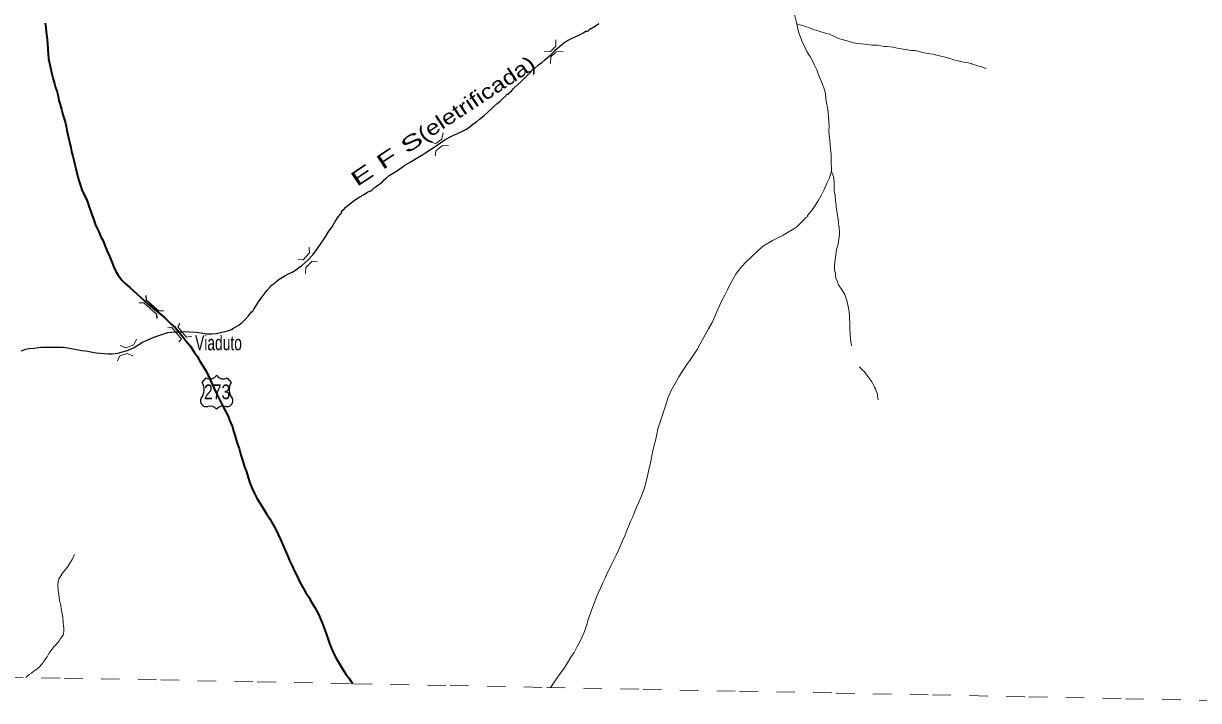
# Model space of a CAD drawing. Extents: x 781.9 to 808.1, y 7453.3 to 7481.5.
# Drawn here: x 787.99 to 794.37, y 7453.56 to 7457.23 of the extents above; entities that cross this region are included whole.
import ezdxf
from ezdxf.enums import TextEntityAlignment as Align

# ---------------------------------------------------------------- set-up
doc = ezdxf.new("R2010")
doc.units = 0
doc.header["$LTSCALE"] = 0.032
for name, pattern in [('DOTTED', [1.5, 0.3, -1.2]), ('LONG_DASHED', [7.5, 6, -1.5]), ('MEDIUM_DASHED', [4.5, 3, -1.5]), ('SHORT_DASHED', [2.7, 1.5, -1.2])]:
    doc.linetypes.add(name, pattern=pattern)
for name, color, linetype, lineweight in [('10', 7, 'Continuous', 25), ('11', 7, 'Continuous', 13), ('12', 7, 'Continuous', 25), ('15', 7, 'Continuous', 25), ('2', 7, 'Continuous', 35), ('35', 7, 'SHORT_DASHED', 13), ('5', 7, 'LONG_DASHED', 13), ('6', 7, 'MEDIUM_DASHED', 13), ('7', 7, 'DOTTED', 13)]:
    doc.layers.add(name, color=color, linetype=linetype, lineweight=lineweight)
doc.layers.add('61', color=7, linetype='Continuous')

msp = doc.modelspace()

# ---------------------------------------------------------------- linework, layer by layer
at = {"layer": '10'}
for p, q in [((788.657, 7455.7586), (788.6587, 7455.7337)), ((788.7282, 7455.6727), (788.6587, 7455.7337)), ((788.715, 7455.6576), (788.7165, 7455.6328)), ((788.753, 7455.6743), (788.7282, 7455.6727))]:
    msp.add_line(p, q, dxfattribs=at)
msp.add_lwpolyline([(788.715, 7455.6576), (788.6455, 7455.7187), (788.6205, 7455.7171)], dxfattribs=at)
at = {"layer": '11'}
for points in [[(790.8811, 7457.1447), (790.8806, 7457.1107), (790.8528, 7457.082), (790.8178, 7457.0834)], [(790.8532, 7457.0173), (790.8547, 7457.0532), (790.8835, 7457.081), (790.9213, 7457.0815)], [(790.195, 7456.5928), (790.2309, 7456.5838), (790.2624, 7456.6065), (790.2705, 7456.6399)], [(790.2986, 7456.5709), (790.2662, 7456.5716), (790.2294, 7456.544), (790.2263, 7456.5159)], [(789.4827, 7455.9531), (789.5104, 7455.9511), (789.5448, 7455.9901), (789.5428, 7456.0213)], [(789.5882, 7455.9414), (789.5599, 7455.944), (789.5244, 7455.9102), (789.5229, 7455.8784)], [(788.818, 7455.5608), (788.7961, 7455.587), (788.7759, 7455.5831)], [(788.8364, 7455.5069), (788.8503, 7455.5221), (788.818, 7455.5608)], [(788.8418, 7455.6062), (788.83, 7455.589), (788.8525, 7455.5619)], [(788.8525, 7455.5619), (788.8777, 7455.5317), (788.907, 7455.5383)], [(788.5186, 7455.4877), (788.5492, 7455.4746), (788.5915, 7455.49), (788.606, 7455.5212)], [(788.5037, 7455.4044), (788.5168, 7455.4316), (788.5551, 7455.4437), (788.5864, 7455.4306)]]:
    msp.add_lwpolyline(points, dxfattribs=at)
at = {"layer": '12'}
for p, q in [((788.9632, 7455.2866), (788.9841, 7455.3109)), ((788.9632, 7455.2866), (788.9841, 7455.3109)), ((789.0412, 7455.324), (789.0416, 7455.3236)), ((789.0412, 7455.324), (789.0416, 7455.3236)), ((789.0984, 7455.3109), (789.1193, 7455.2868)), ((789.0984, 7455.3109), (789.1193, 7455.2868))]:
    msp.add_line(p, q, dxfattribs=at)
for centre, radius, start, end in [((789.0049, 7455.351), 0.0452, 242.52866, 323.41613), ((789.0049, 7455.351), 0.0452, 242.52866, 323.41613), ((789.0775, 7455.351), 0.0452, 217.23651, 297.49117), ((789.0775, 7455.351), 0.0452, 217.23651, 297.49117), ((788.9, 7455.2484), 0.0738, 320.67544, 31.14191), ((788.9, 7455.2484), 0.0738, 320.67544, 31.14191), ((789.1824, 7455.2484), 0.0738, 148.68696, 219.32477), ((789.1824, 7455.2484), 0.0738, 148.68696, 219.32477), ((788.9852, 7455.1868), 0.0316, 151.50035, 286.50661), ((788.9852, 7455.1868), 0.0316, 151.50035, 286.50661), ((789.0973, 7455.1868), 0.0316, 253.49417, 28.49965), ((789.0973, 7455.1868), 0.0316, 253.49417, 28.49965), ((789.0072, 7455.1151), 0.0433, 38.34716, 107.68663), ((789.0072, 7455.1151), 0.0433, 38.34716, 107.68663), ((789.0752, 7455.1151), 0.0433, 72.31281, 141.65284), ((789.0752, 7455.1151), 0.0433, 72.31281, 141.65284)]:
    msp.add_arc(centre, radius, start, end, dxfattribs=at)
at = {"layer": '15'}
for points in [[(790.6156, 7456.8521), (790.6253, 7456.8496), (790.627, 7456.8561), (790.6351, 7456.8634), (790.64, 7456.8675), (790.6521, 7456.8813), (790.6756, 7456.9032), (790.6927, 7456.9186), (790.7073, 7456.934), (790.7219, 7456.9486), (790.7437, 7456.968), (790.7478, 7456.9737), (790.751, 7456.9818), (790.7551, 7456.9818), (790.7584, 7456.9859), (790.764, 7456.9875), (790.7875, 7457.0102), (790.8054, 7457.0231), (790.8216, 7457.037), (790.8561, 7457.0666), (790.8785, 7457.0898), (790.9114, 7457.1178), (790.921, 7457.125), (790.9221, 7457.1269), (790.9448, 7457.1424), (790.9659, 7457.1529), (790.9862, 7457.1618), (791.0065, 7457.1707), (791.0283, 7457.1813), (791.0461, 7457.1942), (791.0502, 7457.191), (791.0591, 7457.1934), (791.0624, 7457.2007), (791.0705, 7457.2064), (791.0737, 7457.2072), (791.0778, 7457.2104), (791.0859, 7457.2145), (791.0891, 7457.2161), (791.0973, 7457.2218), (791.1151, 7457.234)], [(790.5321, 7456.7718), (790.5476, 7456.7856), (790.5637, 7456.7994), (790.5792, 7456.8132), (790.5946, 7456.827), (790.6108, 7456.8416), (790.6156, 7456.8521)], [(788.8525, 7455.5619), (788.8597, 7455.5622), (788.9302, 7455.559), (788.9903, 7455.5502), (789.0144, 7455.5502), (789.0384, 7455.5526), (789.0622, 7455.5573), (789.0849, 7455.5622), (789.1068, 7455.5687), (789.1182, 7455.5727), (789.1222, 7455.5743), (789.1246, 7455.5735), (789.1287, 7455.5792), (789.1579, 7455.5954), (789.1774, 7455.61), (789.1952, 7455.6278), (789.2114, 7455.6457), (789.2325, 7455.6708), (789.2357, 7455.67), (789.2406, 7455.6813), (789.2681, 7455.7235), (789.2819, 7455.743), (789.299, 7455.7657), (789.3152, 7455.7867), (789.3338, 7455.807), (789.3395, 7455.8143), (789.346, 7455.8176), (789.3709, 7455.8392), (789.3885, 7455.852), (789.4077, 7455.8632), (789.4303, 7455.8751), (789.4514, 7455.8857), (789.4684, 7455.8962), (789.4855, 7455.9084), (789.5033, 7455.9213), (789.5354, 7455.9501), (789.5634, 7455.9797), (789.5891, 7456.0125), (789.6051, 7456.0365), (789.6316, 7456.0757), (789.6493, 7456.1069), (789.6671, 7456.1305), (789.6841, 7456.1589), (789.7027, 7456.1864), (789.7206, 7456.2092), (789.7206, 7456.2124), (789.7181, 7456.2132), (789.7198, 7456.2197), (789.7279, 7456.2213), (789.7311, 7456.227), (789.7359, 7456.2286), (789.7367, 7456.2335), (789.7611, 7456.2546), (789.7806, 7456.2683), (789.7992, 7456.2821), (789.8179, 7456.2927), (789.8381, 7456.304), (789.8568, 7456.317), (789.8746, 7456.3267), (789.8762, 7456.3251), (789.8843, 7456.3316), (789.8843, 7456.3324), (789.8884, 7456.3357), (789.8981, 7456.3437), (789.9038, 7456.3478), (789.9168, 7456.3567), (789.9265, 7456.364), (789.9403, 7456.3754), (789.9508, 7456.3851), (789.9613, 7456.3957), (789.9768, 7456.4094), (790.0033, 7456.4262), (790.0281, 7456.4398), (790.0626, 7456.4646), (790.087, 7456.4792), (790.1048, 7456.4905), (790.1227, 7456.501), (790.1413, 7456.5124), (790.16, 7456.5237), (790.1714, 7456.5308), (790.2068, 7456.554), (790.2427, 7456.578), (790.2804, 7456.6044), (790.3148, 7456.6228), (790.3469, 7456.6372), (790.3749, 7456.6492), (790.3958, 7456.6604), (790.4178, 7456.6762), (790.4332, 7456.6892), (790.4503, 7456.7013), (790.4673, 7456.7143), (790.4922, 7456.7343), (790.513, 7456.7535), (790.5321, 7456.7718)], [(788.6395, 7455.5058), (788.6633, 7455.516), (788.6836, 7455.5257), (788.7055, 7455.5346), (788.7282, 7455.5411), (788.7379, 7455.5446), (788.7772, 7455.5574)], [(788.7772, 7455.5574), (788.8116, 7455.5606), (788.818, 7455.5608), (788.8368, 7455.5614), (788.8525, 7455.5619)], [(787.9808, 7455.458), (788.0057, 7455.4668), (788.0217, 7455.47), (788.0513, 7455.4732), (788.0882, 7455.478), (788.1153, 7455.4787), (788.1396, 7455.4787), (788.1639, 7455.4787), (788.1866, 7455.4779), (788.2093, 7455.4779), (788.2336, 7455.4738), (788.2904, 7455.4641), (788.3099, 7455.4608), (788.3293, 7455.4584), (788.3488, 7455.4552), (788.3682, 7455.4511), (788.3877, 7455.4471), (788.4071, 7455.4446), (788.4542, 7455.4422), (788.472, 7455.4422), (788.4898, 7455.4438), (788.5061, 7455.4462), (788.5161, 7455.4482), (788.5578, 7455.4602), (788.593, 7455.4754), (788.6187, 7455.4922), (788.6395, 7455.5058)]]:
    msp.add_lwpolyline(points, dxfattribs=at)
at = {"layer": '2'}
for points in [[(788.1104, 7457.2364), (788.1136, 7457.2121), (788.1161, 7457.1894), (788.1218, 7457.1486), (788.1242, 7457.1238), (788.1267, 7457.067), (788.1284, 7457.043), (788.1372, 7457.003), (788.1436, 7456.977), (788.1485, 7456.9543), (788.155, 7456.9316), (788.1607, 7456.9089), (788.1671, 7456.8862), (788.1761, 7456.8618), (788.1817, 7456.8391), (788.1858, 7456.8164), (788.1931, 7456.7937), (788.1996, 7456.7694), (788.2052, 7456.7451), (788.2126, 7456.7224), (788.219, 7456.6997), (788.2239, 7456.677), (788.2288, 7456.6543), (788.2336, 7456.63), (788.2385, 7456.6073), (788.2442, 7456.5846), (788.2499, 7456.5619), (788.2539, 7456.5392), (788.2612, 7456.5148), (788.2661, 7456.4921), (788.2709, 7456.4694), (788.2774, 7456.4467), (788.2831, 7456.424), (788.2888, 7456.3997), (788.2953, 7456.377), (788.3025, 7456.3543), (788.309, 7456.3316), (788.3204, 7456.3089), (788.3333, 7456.2846), (788.3431, 7456.2603), (788.3496, 7456.2376), (788.3577, 7456.2149), (788.365, 7456.1922), (788.3747, 7456.1695), (788.382, 7456.1451), (788.3925, 7456.1224), (788.4031, 7456.0997), (788.412, 7456.077)], [(788.412, 7456.077), (788.425, 7456.0543), (788.4339, 7456.03), (788.4444, 7456.0073), (788.4461, 7456.0016), (788.459, 7455.9716), (788.4736, 7455.936)], [(788.4736, 7455.936), (788.4825, 7455.9116), (788.4939, 7455.8889), (788.5077, 7455.8694), (788.5271, 7455.8419), (788.5433, 7455.8249), (788.5701, 7455.8021), (788.5895, 7455.7843), (788.6082, 7455.7665), (788.6285, 7455.7486), (788.6495, 7455.73), (788.6706, 7455.7097), (788.6925, 7455.6911), (788.7144, 7455.6724), (788.7363, 7455.6562), (788.7557, 7455.64), (788.7744, 7455.6221), (788.7946, 7455.6035), (788.8166, 7455.584), (788.8368, 7455.5614)], [(788.8368, 7455.5614), (788.8384, 7455.5597), (788.8604, 7455.5322), (788.8749, 7455.5111), (788.8984, 7455.4827), (788.9195, 7455.4511), (788.935, 7455.43), (788.9503, 7455.4025), (788.9633, 7455.3814), (788.9819, 7455.3506), (788.9933, 7455.3279), (788.9982, 7455.3187), (789.0159, 7455.2811), (789.0359, 7455.2347), (789.0736, 7455.1611), (789.1065, 7455.0963), (789.1092, 7455.0879), (789.1157, 7455.0701), (789.1263, 7455.0457), (789.1328, 7455.023), (789.1392, 7455.0003), (789.1474, 7454.976), (789.1547, 7454.9517), (789.1627, 7454.9274), (789.1716, 7454.8914), (789.1828, 7454.8594), (789.1928, 7454.8285), (789.2025, 7454.8009), (789.2122, 7454.7717), (789.2211, 7454.7425), (789.2317, 7454.7149), (789.2446, 7454.6874), (789.26, 7454.6582), (789.2779, 7454.629), (789.2949, 7454.6014), (789.3111, 7454.5739), (789.3289, 7454.5463), (789.3452, 7454.5171), (789.3622, 7454.4896), (789.3743, 7454.462), (789.3881, 7454.4344), (789.4003, 7454.4052), (789.4133, 7454.376), (789.4254, 7454.3485), (789.4368, 7454.3209), (789.4506, 7454.2917), (789.4635, 7454.2625), (789.4773, 7454.235), (789.4911, 7454.2074), (789.5065, 7454.1782), (789.5235, 7454.149), (789.5414, 7454.1215), (789.556, 7454.0939), (789.5738, 7454.0663), (789.5939, 7454.0295), (789.6139, 7453.9831), (789.6354, 7453.9253), (789.6443, 7453.8977), (789.6533, 7453.8701), (789.6638, 7453.8426), (789.6767, 7453.815), (789.6922, 7453.7874), (789.7068, 7453.7599), (789.7246, 7453.7323), (789.7416, 7453.7047), (789.7611, 7453.678), (789.7765, 7453.6553), (789.7789, 7453.6524)]]:
    msp.add_lwpolyline(points, dxfattribs=at)
at = {"layer": '35'}
msp.add_lwpolyline([(794.4714, 7453.5611), (793.9481, 7453.5713), (793.4247, 7453.5816), (792.9014, 7453.5918), (792.378, 7453.602), (791.8547, 7453.6122), (791.3314, 7453.6223), (790.808, 7453.6325), (790.2847, 7453.6426), (789.7614, 7453.6527), (789.238, 7453.6628), (788.7147, 7453.6729), (788.1914, 7453.6829), (787.668, 7453.6929)], dxfattribs=at)
at = {"layer": '5'}
for points in [[(792.0097, 7457.6862), (792.0233, 7457.6598), (792.0312, 7457.645), (792.0442, 7457.624), (792.0564, 7457.6029), (792.0677, 7457.5802), (792.0815, 7457.5575), (792.0912, 7457.5364), (792.1018, 7457.5153), (792.1099, 7457.4942), (792.118, 7457.4715), (792.1253, 7457.4488), (792.1326, 7457.4278), (792.1391, 7457.4067), (792.1456, 7457.3856), (792.152, 7457.3645), (792.1585, 7457.3418), (792.1642, 7457.3207), (792.1707, 7457.2997), (792.1779, 7457.2755), (792.1883, 7457.2315)], [(792.1883, 7457.2315), (792.1971, 7457.1883), (792.2163, 7457.1395), (792.2307, 7457.1083), (792.2436, 7457.0824), (792.259, 7457.0564), (792.2728, 7457.0321), (792.2842, 7457.0078), (792.2972, 7456.9818), (792.3061, 7456.9559), (792.3174, 7456.93), (792.3272, 7456.9056), (792.3361, 7456.8797), (792.3434, 7456.8537), (792.3466, 7456.8278), (792.3491, 7456.8035), (792.3547, 7456.7791), (792.3588, 7456.7532), (792.3604, 7456.7273), (792.362, 7456.7013), (792.3637, 7456.677), (792.3629, 7456.6527), (792.3645, 7456.6267), (792.3669, 7456.6008), (792.3702, 7456.5748), (792.3718, 7456.5505), (792.3742, 7456.5262), (792.3758, 7456.5002), (792.3758, 7456.4743), (792.3766, 7456.4484), (792.3775, 7456.4305)], [(792.3775, 7456.4305), (792.3734, 7456.4224), (792.3653, 7456.3965), (792.3539, 7456.3705), (792.3393, 7456.3373), (792.3223, 7456.3048), (792.3045, 7456.2724), (792.285, 7456.2408), (792.2688, 7456.2181), (792.2469, 7456.1922), (792.2477, 7456.1873), (792.238, 7456.1816), (792.2275, 7456.1687), (792.1893, 7456.1313), (792.1723, 7456.1208), (792.1334, 7456.0964), (792.1083, 7456.0827), (792.0896, 7456.073), (792.0568, 7456.0573), (792.0087, 7456.0285), (791.9799, 7456.0037), (791.943, 7455.9677), (791.9413, 7455.9659), (791.9077, 7455.9347), (791.878, 7455.9003), (791.8577, 7455.8743), (791.8423, 7455.8451), (791.8261, 7455.816), (791.8123, 7455.7884), (791.7977, 7455.7608), (791.7823, 7455.7316), (791.7693, 7455.7025), (791.7564, 7455.6749), (791.7442, 7455.6441), (791.7298, 7455.6113), (791.709, 7455.5777), (791.6634, 7455.4961), (791.6477, 7455.4657), (791.6291, 7455.4381), (791.6112, 7455.4106), (791.5918, 7455.3846), (791.5699, 7455.3505), (791.5488, 7455.3173), (791.5286, 7455.2809), (791.5078, 7455.2425)], [(791.5078, 7455.2425), (791.4894, 7455.2017), (791.4791, 7455.1706), (791.4702, 7455.143), (791.4613, 7455.1155), (791.4523, 7455.0895), (791.4434, 7455.062)], [(791.4434, 7455.062), (791.4353, 7455.0344), (791.4288, 7455.0068), (791.4232, 7454.9793), (791.4159, 7454.9517), (791.4094, 7454.9241), (791.4045, 7454.8966), (791.3988, 7454.869), (791.3923, 7454.8414), (791.3859, 7454.8139), (791.3802, 7454.7863), (791.3722, 7454.7487), (791.3602, 7454.7103), (791.3426, 7454.6623), (791.3299, 7454.6339), (791.3186, 7454.6095), (791.308, 7454.5836), (791.2983, 7454.5577), (791.2869, 7454.5317), (791.2756, 7454.5058), (791.2651, 7454.4798), (791.2553, 7454.4539), (791.2432, 7454.4279), (791.2318, 7454.402), (791.2205, 7454.376), (791.2091, 7454.3501), (791.1953, 7454.3242), (791.184, 7454.2982), (791.171, 7454.2723), (791.1588, 7454.2479), (791.1475, 7454.222), (791.1353, 7454.1961), (791.1232, 7454.1701), (791.1102, 7454.1442), (791.1005, 7454.1182), (791.0907, 7454.0923), (791.081, 7454.0663), (791.0713, 7454.0404), (791.0616, 7454.0144), (791.0583, 7454.0055), (791.0486, 7453.9739), (791.0364, 7453.9358), (791.0218, 7453.9026), (791.0105, 7453.8766), (790.9959, 7453.8507), (790.9829, 7453.8247), (790.9805, 7453.8207), (790.9635, 7453.7963), (790.9383, 7453.7566), (790.9221, 7453.7307), (790.9043, 7453.7071), (790.8856, 7453.6779), (790.8646, 7453.6496), (790.854, 7453.6342), (790.8522, 7453.6316)]]:
    msp.add_lwpolyline(points, dxfattribs=at)
at = {"layer": '6'}
for points in [[(793.2158, 7456.9883), (793.2117, 7456.9899), (793.1923, 7456.998), (793.1704, 7457.0045), (793.1363, 7457.0159), (793.1339, 7457.0167), (793.1177, 7457.0207), (793.1015, 7457.0231), (793.0853, 7457.0264), (793.0707, 7457.0304), (793.0561, 7457.0337), (793.039, 7457.0361), (793.0317, 7457.041), (793.0188, 7457.0434), (792.9888, 7457.0532), (792.9863, 7457.0531), (792.9701, 7457.0564), (792.9555, 7457.0605), (792.9409, 7457.0645), (792.9263, 7457.0677), (792.9117, 7457.0694), (792.8972, 7457.071), (792.8745, 7457.0767), (792.8299, 7457.0872), (792.8258, 7457.0872), (792.8112, 7457.0872), (792.7966, 7457.0888), (792.782, 7457.0921), (792.7658, 7457.0945), (792.7496, 7457.0977), (792.7334, 7457.101), (792.7091, 7457.105), (792.679, 7457.1083), (792.675, 7457.1083), (792.6604, 7457.1099), (792.6442, 7457.1131), (792.628, 7457.1156), (792.6118, 7457.1164), (792.5956, 7457.1172), (792.5712, 7457.1204), (792.5396, 7457.1229), (792.5258, 7457.1253), (792.5096, 7457.1269), (792.4934, 7457.1294), (792.4772, 7457.1342), (792.4626, 7457.1391), (792.448, 7457.1432), (792.4447, 7457.1439), (792.4382, 7457.1464), (792.4269, 7457.1496), (792.4147, 7457.1521), (792.3896, 7457.165), (792.3653, 7457.1756), (792.3491, 7457.1796), (792.3329, 7457.1853), (792.3183, 7457.1894), (792.3037, 7457.1934), (792.2891, 7457.1983), (792.2802, 7457.2007), (792.255, 7457.2104), (792.2364, 7457.2177), (792.2116, 7457.2257), (792.1883, 7457.2315)], [(792.3775, 7456.4305), (792.388, 7456.4042), (792.3904, 7456.3738), (792.3912, 7456.3576), (792.392, 7456.3275), (792.3936, 7456.3154), (792.3961, 7456.304), (792.3968, 7456.2927), (792.3993, 7456.2813), (792.3993, 7456.27), (792.4001, 7456.2603), (792.4026, 7456.2505), (792.4017, 7456.2408), (792.4042, 7456.2246), (792.4091, 7456.1946), (792.409, 7456.1922), (792.4115, 7456.1808), (792.4131, 7456.1695), (792.4147, 7456.1581), (792.4155, 7456.1468), (792.4171, 7456.137), (792.4179, 7456.1273), (792.4188, 7456.1176), (792.4204, 7456.1062), (792.4204, 7456.0949), (792.4204, 7456.0876), (792.4174, 7456.0632), (792.4126, 7456.0368), (792.4046, 7456.0064), (792.3929, 7455.9254)], [(792.3929, 7455.9254), (792.3928, 7455.9197), (792.3936, 7455.9035), (792.3944, 7455.8864), (792.3961, 7455.8857), (792.3977, 7455.8816), (792.3985, 7455.8679), (792.4009, 7455.8516), (792.4074, 7455.8354), (792.4131, 7455.8208), (792.4147, 7455.8168), (792.435, 7455.7876), (792.4496, 7455.7641), (792.4552, 7455.7479), (792.4593, 7455.7316), (792.4634, 7455.7154), (792.4675, 7455.6984), (792.4731, 7455.67), (792.4739, 7455.6457), (792.4747, 7455.6295), (792.4755, 7455.6133), (792.4763, 7455.5971), (792.4755, 7455.5825), (792.4756, 7455.5784), (792.4788, 7455.5468), (792.4804, 7455.5225), (792.482, 7455.5062), (792.4844, 7455.49), (792.4853, 7455.486)], [(792.5292, 7455.3706), (792.5404, 7455.3586), (792.5557, 7455.3434), (792.5789, 7455.3122), (792.5947, 7455.2906), (792.6004, 7455.2792), (792.6044, 7455.2719), (792.6109, 7455.2614), (792.615, 7455.2517), (792.6198, 7455.2419), (792.6231, 7455.2322), (792.6263, 7455.2225), (792.6263, 7455.2128), (792.6279, 7455.2014), (792.6296, 7455.1925)]]:
    msp.add_lwpolyline(points, dxfattribs=at)
at = {"layer": '7'}
msp.add_lwpolyline([(788.0051, 7453.6865), (788.0245, 7453.7014), (788.0374, 7453.7096), (788.0528, 7453.7234), (788.0537, 7453.7242), (788.0601, 7453.7282), (788.0666, 7453.7331), (788.078, 7453.7412), (788.0934, 7453.7574), (788.0966, 7453.7623), (788.1039, 7453.7736), (788.1169, 7453.7899), (788.1217, 7453.7988), (788.1266, 7453.8085), (788.1347, 7453.8207), (788.1469, 7453.8369), (788.1493, 7453.8401), (788.1566, 7453.8498), (788.1671, 7453.8612), (788.1809, 7453.8774), (788.1866, 7453.8855), (788.1947, 7453.8977), (788.2085, 7453.9163), (788.2101, 7453.9253), (788.2125, 7453.935), (788.2125, 7453.9463), (788.2117, 7453.9577), (788.2109, 7453.9617), (788.2065, 7454.0134), (788.1989, 7454.0491), (788.1933, 7454.0852), (788.1915, 7454.0898), (788.1898, 7454.0971), (788.1882, 7454.1069), (788.1866, 7454.1158), (788.1842, 7454.1393), (788.1817, 7454.1555), (788.1818, 7454.1596), (788.1801, 7454.1879), (788.1817, 7454.2042), (788.1842, 7454.2155), (788.1858, 7454.2212), (788.1987, 7454.2431), (788.1996, 7454.2438), (788.1996, 7454.2471), (788.2052, 7454.2512), (788.2297, 7454.2829), (788.257, 7454.3254), (788.2694, 7454.3531)], dxfattribs=at)

# ---------------------------------------------------------------- texts
at = {"layer": '61'}
for s, rotation, width, p in [('(eletrificada)', 33.477, 1.25, (790.4718, 7456.7937)), ('E F S', 33.473, 1.65, (789.9861, 7456.4676))]:
    msp.add_text(s, height=0.08, rotation=rotation, dxfattribs=dict(at, width=width)).set_placement(p, align=Align.CENTER)
for s, width, p in [('Viaduto', 0.7, (789.0512, 7455.4614)), ('273', 0.8, (789.0439, 7455.1957))]:
    msp.add_text(s, height=0.08, dxfattribs=dict(at, width=width)).set_placement(p, align=Align.CENTER)

doc.saveas('drawing.dxf')
